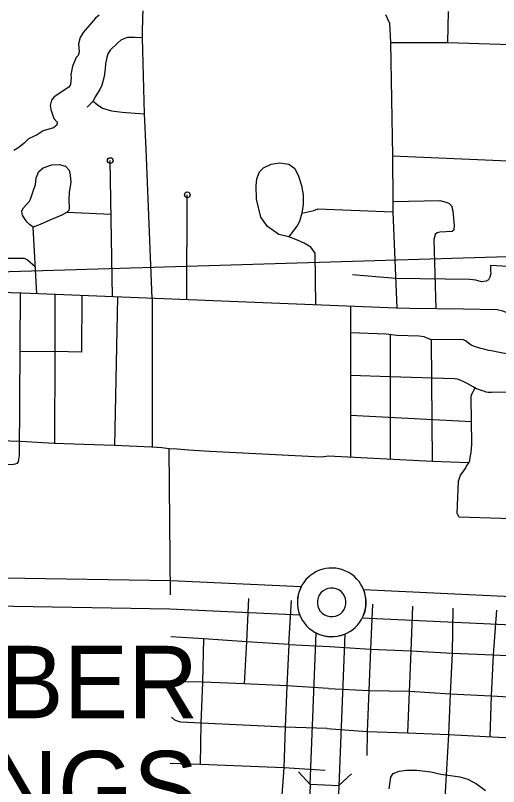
# Model space of a CAD drawing. Extents: x 1212896 to 1368412, y 378476 to 478763.
# Drawn here: x 1298275 to 1302502, y 420570 to 427313 of the extents above; entities that cross this region are included whole.
import ezdxf

# ---------------------------------------------------------------- set-up
doc = ezdxf.new("R2010")
doc.units = 0
for name, color, linetype in [('Level 10', 7, 'Continuous'), ('Level 24', 7, 'Continuous'), ('Level 33', 7, 'Continuous'), ('Level 34', 7, 'Continuous'), ('Level 35', 7, 'Continuous'), ('Level 37', 7, 'Continuous'), ('Level 6', 7, 'Continuous'), ('Level 60', 7, 'Continuous'), ('Level 9', 7, 'Continuous')]:
    doc.layers.add(name, color=color, linetype=linetype)

msp = doc.modelspace()

# ---------------------------------------------------------------- linework, layer by layer
at = {"layer": 'Level 10'}
msp.add_line((1301104.6, 420576.7), (1300854.9, 420589.1), dxfattribs=at)
for points in [[(1301320.2, 422292.8), (1304147.7, 422160.1), (1304233, 422184.8), (1304524.9, 422302.6), (1305075, 422560.6), (1305253.1, 422635.8), (1305725.3, 422854.2), (1305957.8, 422953.9), (1306173.5, 423053), (1306858.2, 423329.3), (1307040.3, 423390.4), (1307270.6, 423456.6), (1307542.5, 423520.2), (1308327.5, 423647.9), (1308845.2, 423714.9), (1310164.8, 423870.3), (1311716.1, 424081.9)], [(1311749.9, 423834.2), (1310196.4, 423622.3), (1308875.9, 423466.8), (1308363.6, 423400.5), (1307591.2, 423274.9), (1307333.7, 423214.6), (1307114.5, 423151.6), (1306944.8, 423094.7), (1306272.5, 422823.4), (1306059.3, 422725.4), (1305827.1, 422625.8), (1305354.2, 422407.1), (1305176.7, 422332.2), (1304624.9, 422073.4), (1304314.8, 421948.2), (1304177.4, 421908.4), (1301308.8, 422043.1)], [(1296711, 422419.3), (1299634.9, 422371.9), (1300775.7, 422318.4)], [(1300763.6, 422068.7), (1299627, 422122), (1296717.2, 422169.2)], [(1300854.9, 420589.1), (1300906.5, 421912.7)], [(1301156.3, 421902.9), (1301104.6, 420576.7)], [(1300854.9, 420589.1), (1300833.9, 420050.8)], [(1301104.6, 420576.7), (1301083.9, 420045)]]:
    msp.add_lwpolyline(points, dxfattribs=at)
for centre, radius, start, end in [((1301042.2, 422180.3), 300.2, 152.61041, 201.83154), ((1301061.1, 422179.4), 282.8, 331.1681, 23.63864), ((1301042.2, 422184.2), 303.5, 243.44595, 292.08706)]:
    msp.add_arc(centre, radius, start, end, dxfattribs=at)
at = {"layer": 'Level 24'}
for radius, start, end in [(300, 330.16001, 150.16001), (300, 150.16001, 330.16001), (125, 330.16001, 150.16001), (125, 150.16001, 330.16001)]:
    msp.add_arc((1301042.1, 422180.3), radius, start, end, dxfattribs=at)
at = {"layer": 'Level 33'}
for points in [[(1299470.7, 424838.4), (1299419.1, 426144.4), (1299404, 426451.1), (1299385.8, 427115.8), (1299386.4, 427186), (1299389.8, 427265.3), (1299391.2, 427297.4), (1299392.1, 427351.6)], [(1301512.7, 427320.2), (1301547.3, 427243.7), (1301557.6, 427075.4), (1301574.3, 426084.6), (1301576.6, 425678.6), (1301576.1, 425595.1), (1301613.2, 424752.1)], [(1302061, 427347.1), (1302055.4, 427075.1)], [(1299385.8, 427115.8), (1299319.8, 427118.5), (1299254.8, 427119.2), (1299223, 427108.5), (1299196.3, 427095), (1299169.7, 427074.4), (1299104, 427008.9), (1299084.7, 426977.4), (1299074.3, 426946.1), (1299064.4, 426890.7), (1299060.3, 426846.5), (1299050.6, 426779.1), (1299031.1, 426703.5), (1299012.9, 426664), (1298974.2, 426600.1), (1298955, 426561.6), (1298904, 426510.4)], [(1301557.6, 427075.4), (1302055.4, 427075.1), (1302890, 427048.4)], [(1298955, 426561.6), (1298990.5, 426534.2), (1299036.1, 426503), (1299116.6, 426478.3), (1299207.8, 426466.2), (1299322.3, 426456.8), (1299404, 426451.1)], [(1299124.8, 424852.3), (1299105.2, 426043.9)], [(1301574.3, 426084.6), (1302857.4, 426029.5), (1303559.1, 426001.3)], [(1298462.1, 424879), (1298429.1, 425461.8), (1298399.3, 425484.7), (1298379.3, 425505), (1298360.9, 425527.7), (1298336.1, 425567.3), (1298332.8, 425580.3), (1298332.4, 425603.3), (1298344.8, 425630.7), (1298375.2, 425663.4), (1298397.6, 425688.9), (1298406.3, 425707.1), (1298436.5, 425795), (1298449.8, 425831.4), (1298456.5, 425893.1), (1298479.5, 425947.3), (1298517.8, 425981.2), (1298593.2, 426005.7), (1298658.1, 426009), (1298712.3, 425993.6), (1298745.2, 425959.3), (1298754.1, 425914.8), (1298758.9, 425856), (1298746, 425765), (1298743.2, 425702.7), (1298746.6, 425631.6), (1298741.1, 425607.4), (1298727.4, 425591.1), (1298682, 425565.1), (1298574.9, 425521.9), (1298490.7, 425485.1), (1298429.1, 425461.8)], [(1299775.1, 424826.2), (1299778.9, 425744.2)], [(1301576.6, 425686.4), (1301986.9, 425693.5), (1302032.1, 425683.4), (1302066.4, 425670), (1302076.7, 425662.8), (1302088.8, 425646.4), (1302102.7, 425604.5), (1302112.3, 425473.3), (1302112.6, 425458.3), (1302111.7, 425452.2), (1302110.1, 425435), (1302096.3, 425423.8), (1301987.4, 425417.7), (1301964.5, 425411.8), (1301946.6, 425396.2), (1301936.7, 425352.5), (1301954, 424748.2)], [(1298727.4, 425591.1), (1299113, 425574.3)], [(1300781.7, 425582.5), (1300886.1, 425607.6), (1300921.8, 425621.3), (1301576.1, 425595.1)], [(1302741.2, 425108.1), (1302432.3, 425125.9), (1302432.7, 425080.8), (1302433, 425056.7), (1302425.3, 425023.6), (1302417.8, 425006.5), (1302412.6, 425000.4), (1302394.7, 424989.4), (1302353.8, 424984.1), (1302303.6, 424997.9), (1302251, 425002.7), (1301601.7, 425013.6)], [(1301601.7, 425013.6), (1301224, 425043.2)], [(1302892.7, 424678.6), (1302766, 424680.5), (1302739.2, 424683.4), (1302717.8, 424686), (1302696.9, 424689.2), (1302671.8, 424693.3), (1302636.7, 424697.5), (1302599.1, 424703.8), (1302540, 424725.8), (1302488.5, 424738.6), (1302194.4, 424744.6), (1301726.9, 424751.5), (1301609.2, 424752.3), (1298331.2, 424884.3), (1297118.9, 424921.4)], [(1302241.2, 423401.5), (1301921.1, 423411.9), (1301013.4, 423457.7), (1300953.2, 423451.4), (1299977.2, 423499.2), (1299788.6, 423512.2), (1299688.8, 423519.2), (1299620.9, 423523.4), (1299555.9, 423530.5), (1299467.1, 423536.8), (1299137.8, 423552.3), (1298614, 423569.7), (1298320.6, 423586.6), (1298038.2, 423595.6), (1298038.2, 423595.6), (1298028.6, 423596.3), (1298016.2, 423599.4), (1297998.2, 423606.2), (1297996.2, 423608.2), (1297986.9, 423616.3), (1297979.5, 423636.4), (1297974.4, 423691.1), (1297980.1, 424302.4), (1297979.9, 424895.1)], [(1298317.1, 424884.7), (1298306.8, 423465.2), (1298303.3, 423430.1), (1298297.8, 423410.1), (1298286.3, 423395.7), (1298273.7, 423388.7), (1298259.8, 423386.5), (1298158, 423384.4), (1298145.1, 423384.3), (1298136.6, 423384), (1298128.1, 423382.1), (1298119.3, 423378.5), (1298108.4, 423370.7), (1298100.4, 423360.8), (1298094.6, 423345.7), (1298088.3, 423277.5), (1298086.4, 422783.5)], [(1298857.2, 424863.1), (1298853.2, 424366.9), (1298618.7, 424374.4)], [(1299168, 424850.6), (1299143.4, 423552.1)], [(1299470.7, 424838.4), (1299472.5, 423536.6)], [(1301207, 424768.5), (1301205.6, 423448)], [(1302943.1, 424336.4), (1302595.8, 424350.1), (1302539.2, 424359), (1302508.9, 424366.2), (1302480, 424370.8), (1302453.9, 424377.6), (1302416.9, 424384.2), (1302373.9, 424393.8), (1302333.9, 424404.4), (1302291.9, 424417.9), (1302269.3, 424427.8), (1302252.9, 424436.4), (1302236.7, 424450.4), (1302213.6, 424466.2), (1302194.5, 424475), (1302158.6, 424478.6), (1301911.5, 424476.8), (1301851.1, 424502.6), (1301807, 424509.1), (1301610.6, 424514.8), (1301518.7, 424525.8), (1301206.8, 424538.4)], [(1301552.8, 424521.7), (1301554.4, 423430.4)], [(1301911.5, 424476.8), (1301921.1, 423411.9)], [(1302927.2, 424005.2), (1302576.3, 424017.2), (1302440.5, 424015.2), (1302411.8, 424015.8), (1302394.4, 424018.8), (1302381.8, 424023), (1302360.9, 424029.6), (1302335.7, 424039.2), (1302309.4, 424048.8), (1302280.6, 424065.6), (1302253.1, 424080.5), (1302227.3, 424095.6), (1302192.3, 424111.2), (1302167.2, 424123), (1302142.2, 424130.7), (1302112.2, 424134.4), (1301552.5, 424151.5), (1301206.3, 424163.5)], [(1302156.5, 422924.5), (1302140.3, 422956.4), (1302151.3, 423241.1), (1302168.7, 423292.3), (1302188.4, 423318.6), (1302188.4, 423319.6), (1302204.2, 423338.8), (1302214.9, 423358), (1302221.8, 423370.1), (1302240.4, 423400.3), (1302251.2, 423419.5), (1302254.9, 423446.6), (1302261.5, 423489.7), (1302266.7, 423564.9), (1302262.5, 423974.7), (1302265.3, 423993.8), (1302270.2, 424003.9), (1302277, 424018), (1302279.9, 424024), (1302298.4, 424055.2)], [(1301206, 423818.3), (1302264.7, 423763.4)], [(1299631, 422247), (1299620.2, 423523.8)], [(1302874.6, 422908.4), (1302521.7, 422914.4), (1302156.5, 422924.5)], [(1300314.7, 422214.7), (1300295.5, 421835.3), (1300276.3, 421469.4)], [(1300667.8, 421812.3), (1300690.1, 422196.9)], [(1301398.6, 422163.5), (1301382.3, 421771.8), (1301367.1, 421409), (1301353.8, 421050.1)], [(1301750.3, 422146.8), (1301734.6, 421756.6), (1301704, 421038.8)], [(1302102.1, 422130.2), (1302095.9, 421737.4), (1302079.6, 421379.6), (1302064.3, 421024.7), (1302001.3, 419962.9), (1301986.9, 419912.6), (1301975.2, 419884.4), (1301969.3, 419873.3), (1301963.5, 419862.3), (1301958.6, 419852.2), (1301948.8, 419835), (1301936, 419814.9), (1301927.2, 419799.7), (1301920.4, 419783.6), (1301912.9, 419735.5), (1301934.4, 419090.4)], [(1300999.1, 421077.5), (1301353.8, 421050.1), (1301704, 421038.8), (1302064.3, 421024.7), (1302779.8, 420988.3), (1303090.2, 420970.6), (1303104.1, 420975.2), (1303113.9, 420980.7), (1303120.7, 420985.8), (1303126, 420990), (1303131.8, 420996.1), (1303133.8, 420999.1), (1303136.6, 421004), (1303138.2, 421009.4), (1303138.6, 421018.2), (1303149.4, 421324.9), (1303162.7, 421683.8), (1303188, 422079.3)], [(1302482.4, 422112.2), (1302455.1, 421721.3), (1302437.8, 421364.4), (1302424.9, 421006.3)], [(1300667.8, 421812.3), (1300295.5, 421835.3), (1299924.2, 421860.4), (1299635.7, 421879.3)], [(1300667.8, 421812.3), (1300650.5, 421449.3), (1300636.2, 421090.5), (1300622, 420732.6), (1300599.3, 420413.7)], [(1300667.8, 421812.3), (1301027, 421794)], [(1301027, 421794), (1301382.3, 421771.8), (1301734.6, 421756.6), (1302095.9, 421737.4), (1302455.1, 421721.3), (1302813.4, 421704.1), (1303162.7, 421683.8), (1303552.9, 421664.9), (1303954, 421650.2)], [(1301012.7, 421426.3), (1300650.5, 421449.3), (1300276.3, 421469.4), (1299915.1, 421481.5), (1299626.8, 421486.4)], [(1299895.5, 420761.8), (1299899.8, 421123.6), (1299915.1, 421481.5)], [(1301012.7, 421426.3), (1301367.1, 421409), (1301721.3, 421402.7), (1302079.6, 421379.6), (1302437.8, 421364.4), (1302796.1, 421343.2), (1303149.4, 421324.9), (1303542.5, 421316.1)], [(1300999.1, 421077.5), (1300636.2, 421090.5), (1299899.8, 421123.6), (1299721.2, 421132.7), (1299692.1, 421140.4), (1299671.1, 421151.2), (1299641.2, 421175.9)], [(1300984.7, 420709.8), (1300622, 420732.6), (1299895.5, 420761.8), (1299628.2, 420770.9)]]:
    msp.add_lwpolyline(points, dxfattribs=at)
for centre in [(1299105.2, 426043.9), (1299778.9, 425744.2)]:
    msp.add_circle(centre, 25, dxfattribs=at)
at = {"layer": 'Level 34'}
for points in [[(1300904.1, 424780.7), (1300897, 425233.8), (1300859.5, 425287.1), (1300799.9, 425320), (1300729.3, 425353.7), (1300666.8, 425377.6), (1300579.3, 425398.4), (1300479.3, 425467.5), (1300422.5, 425548.3), (1300384.4, 425707), (1300380.1, 425822.3), (1300387.8, 425884.6), (1300411.6, 425946.3), (1300445.9, 425979.1), (1300512.2, 426012.5), (1300585, 426023), (1300666.2, 426013.5), (1300718.9, 425973.4), (1300751.3, 425905.9), (1300778.8, 425827), (1300793.8, 425743.4), (1300792.1, 425659.9), (1300781.7, 425582.5), (1300761.1, 425509.8), (1300743.8, 425479.4), (1300666.8, 425377.6)], [(1297978.8, 425189.1), (1298351.6, 425189.4), (1298381.9, 425176), (1298448.6, 425118.4)], [(1298621.2, 424872.6), (1298618.7, 424374.4), (1298618.2, 423569.5)], [(1298313.5, 424378.3), (1298618.7, 424374.4)], [(1299915.1, 421481.5), (1299924.2, 421860.4)], [(1301353.8, 421050.1), (1301350, 420842.6)]]:
    msp.add_lwpolyline(points, dxfattribs=at)
at = {"layer": 'Level 35'}
msp.add_lwpolyline([(1301544, 420549.7), (1301558.4, 420653), (1301579.5, 420684.3), (1301633.3, 420704.1), (1301699.8, 420713.3), (1301787.7, 420713.6), (1301908.5, 420699.9), (1301996.5, 420678.8), (1302164.3, 420655.6), (1302232.3, 420635.2), (1302308.6, 420594), (1302387, 420534.7)], dxfattribs=at)
at = {"layer": 'Level 37'}
for points in [[(1300854.9, 420587.8), (1300753, 420697.9)], [(1301214.8, 420679.9), (1301104.7, 420578)]]:
    msp.add_lwpolyline(points, dxfattribs=at)
at = {"layer": 'Level 60'}
msp.add_spline([(1257400.5, 423880.1), (1274492.7, 424373.3), (1311685.6, 425480.9), (1319317.4, 425714)], degree=3, dxfattribs=at)
at = {"layer": 'Level 9'}
msp.add_lwpolyline([(1299006.6, 427314.6), (1298977.1, 427290), (1298868.6, 427164.5), (1298841.5, 427119.8), (1298827.7, 427064.4), (1298833.5, 426990.3), (1298822.7, 426963), (1298807.5, 426944.9), (1298773.5, 426869.7), (1298760.1, 426794.3), (1298763.5, 426770.3), (1298756.8, 426707.9), (1298742.2, 426685.6), (1298614, 426599.8), (1298591.5, 426571.3), (1298580.5, 426523.9), (1298584.2, 426488.9), (1298609.8, 426411.8), (1298640.4, 426378.7), (1298638.9, 426354.6), (1298607.3, 426330.9), (1298517.4, 426303.9), (1298464.6, 426267.9), (1298388.3, 426234.3), (1298353.1, 426194.5), (1298304.9, 426157.4), (1298261.4, 426131.5)], dxfattribs=at)

# ---------------------------------------------------------------- texts
at = {"layer": 'Level 6'}
for s, p in [('HEBER', (1296954.2, 421166.8)), ('SPRINGS', (1296057.4, 420247.8))]:
    msp.add_text(s, height=633.6, dxfattribs=at).set_placement(p)

doc.saveas('drawing.dxf')
